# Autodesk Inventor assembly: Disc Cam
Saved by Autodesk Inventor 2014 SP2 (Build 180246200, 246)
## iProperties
Created: 2016-02
Part Number: Disc Cam
Document SubType Name: Assembly
Designer: User
ClientObjectVersion: 1
Author: User
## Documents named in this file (2)
- D:\SFC\3-Autodesk\2014-01-30 GrabCAD\67 - Oscillating Cam Mechanism\Oscillating Cam Mechanism\Design Accelerator\Disc Cam1.iam
- D:\SFC\3-Autodesk\2014-01-30 GrabCAD\67 - Oscillating Cam Mechanism\Oscillating Cam Mechanism\Design Accelerator\Disc Cam1.ipt
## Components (1 placed, 1 different names)
1. Disc Cam:1
